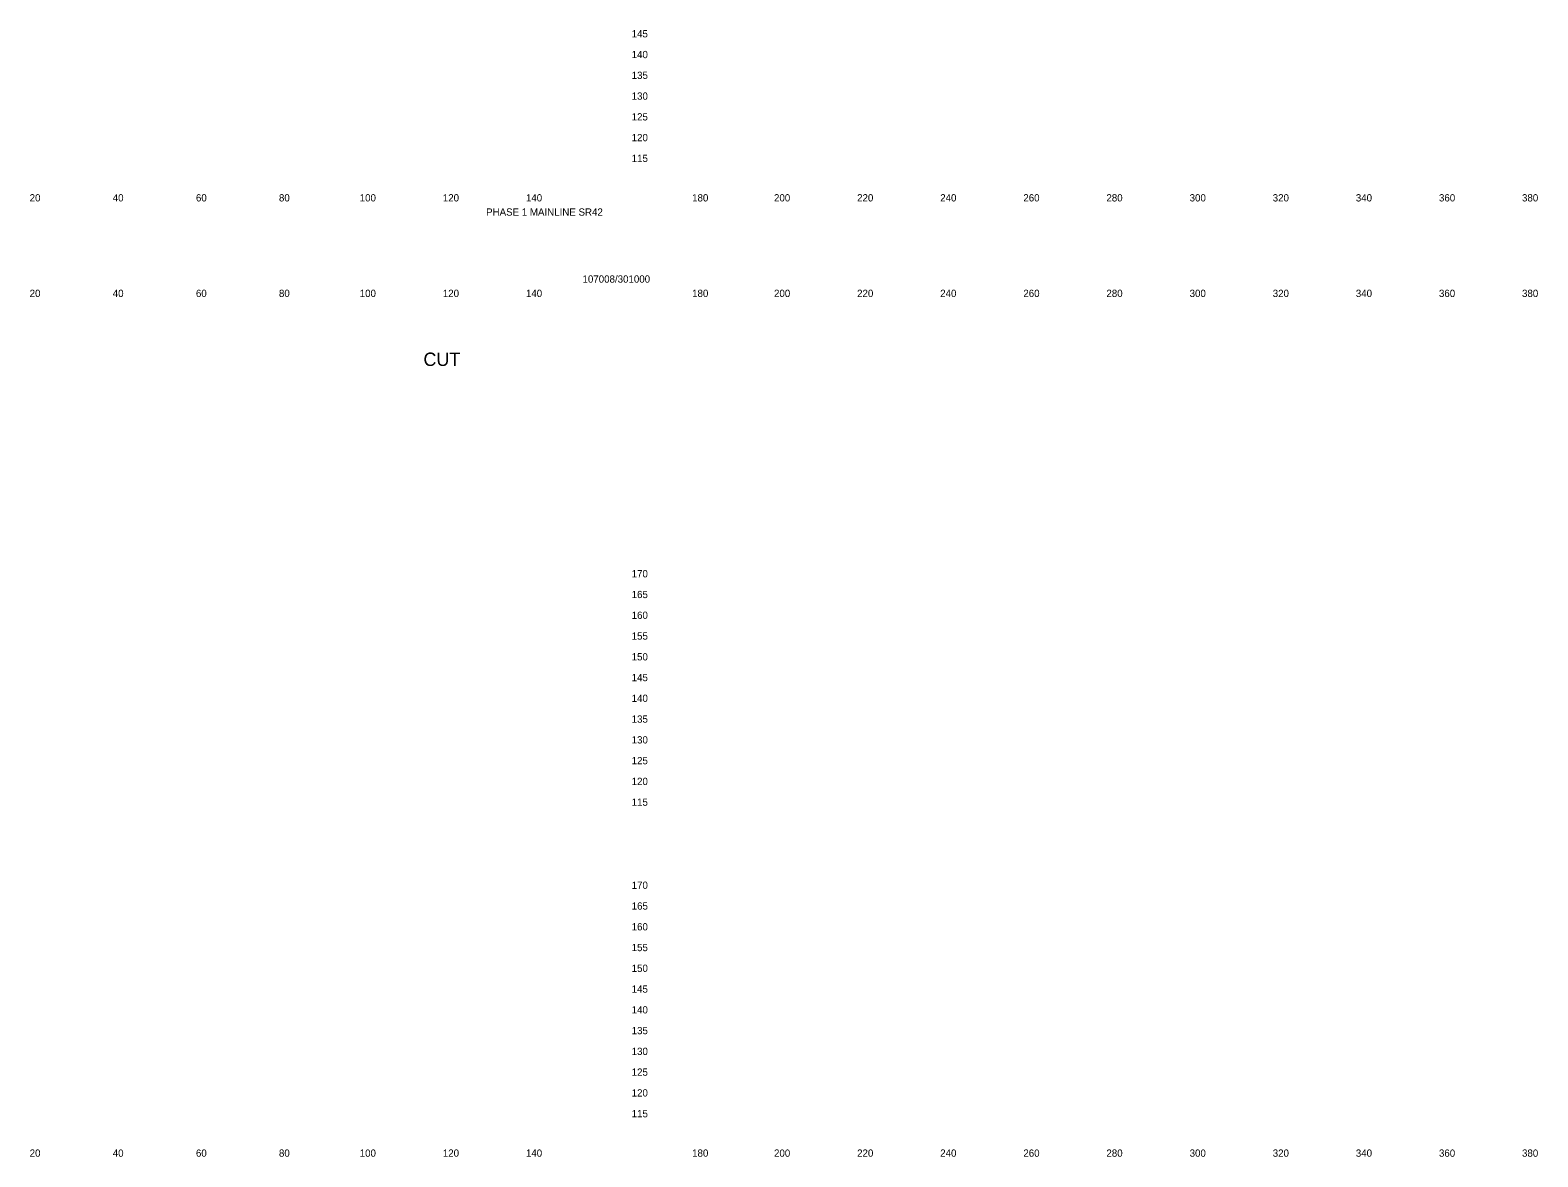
# Model space of a CAD drawing. Extents: x 21281 to 22024, y 6472 to 15198.
# Drawn here: x 21661.4 to 22024.2, y 13835.3 to 14106.6 of the extents above; entities that cross this region are included whole.
import ezdxf

# ---------------------------------------------------------------- set-up
doc = ezdxf.new("R2010")
doc.units = 0
doc.layers.add('XS_SHEET_LABELS_ELEVATION', color=7, linetype='Continuous')
doc.layers.add('XS_SHEET_LABELS_OFFSET', color=7, linetype='Continuous')

msp = doc.modelspace()

# ---------------------------------------------------------------- texts
at = {"layer": 'XS_SHEET_LABELS_ELEVATION'}
for s, p in [('  145  ', (21804.84, 14104.84)), ('  140  ', (21804.84, 14099.84)), ('  135  ', (21804.84, 14094.84)), ('  130  ', (21804.84, 14089.84)), ('  125  ', (21804.84, 14084.84)), ('  120  ', (21804.84, 14079.84)), ('  115  ', (21804.84, 14074.84)), ('  170  ', (21804.84, 13974.84)), ('  165  ', (21804.84, 13969.84)), ('  160  ', (21804.84, 13964.84)), ('  155  ', (21804.84, 13959.84)), ('  150  ', (21804.84, 13954.84)), ('  145  ', (21804.84, 13949.84)), ('  140  ', (21804.84, 13944.84)), ('  135  ', (21804.84, 13939.84)), ('  130  ', (21804.84, 13934.84)), ('  125  ', (21804.84, 13929.84)), ('  120  ', (21804.84, 13924.84)), ('  115  ', (21804.84, 13919.84)), ('  170  ', (21804.84, 13899.84)), ('  165  ', (21804.84, 13894.84)), ('  160  ', (21804.84, 13889.84)), ('  155  ', (21804.84, 13884.84)), ('  150  ', (21804.84, 13879.84)), ('  145  ', (21804.84, 13874.84)), ('  140  ', (21804.84, 13869.84)), ('  135  ', (21804.84, 13864.84)), ('  130  ', (21804.84, 13859.84)), ('  125  ', (21804.84, 13854.84)), ('  120  ', (21804.84, 13849.84)), ('  115  ', (21804.84, 13844.84))]:
    msp.add_text(s, height=1.75, dxfattribs=at).set_placement(p)
at = {"layer": 'XS_SHEET_LABELS_OFFSET'}
for s, height, p in [('  20  ', 1.75, (21659.95, 14065.34)), ('  40  ', 1.75, (21679.95, 14065.34)), ('  60  ', 1.75, (21699.97, 14065.34)), ('  80  ', 1.75, (21719.95, 14065.34)), ('  100  ', 1.75, (21739.39, 14065.34)), ('  120  ', 1.75, (21759.39, 14065.34)), ('  140  ', 1.75, (21779.39, 14065.34)), ('  180  ', 1.75, (21819.39, 14065.34)), ('  200  ', 1.75, (21839.1, 14065.34)), ('  220  ', 1.75, (21859.1, 14065.34)), ('  240  ', 1.75, (21879.1, 14065.34)), ('  260  ', 1.75, (21899.11, 14065.34)), ('  280  ', 1.75, (21919.1, 14065.34)), ('  300  ', 1.75, (21939.13, 14065.34)), ('  320  ', 1.75, (21959.13, 14065.34)), ('  340  ', 1.75, (21979.13, 14065.34)), ('  360  ', 1.75, (21999.14, 14065.34)), ('  380  ', 1.75, (22019.13, 14065.34)), ('PHASE 1 MAINLINE SR42', 1.75, (21771.11, 14061.92)), ('107008/301000', 1.75, (21794.31, 14045.79)), ('  20  ', 1.75, (21659.95, 14042.34)), ('  40  ', 1.75, (21679.95, 14042.34)), ('  60  ', 1.75, (21699.97, 14042.34)), ('  80  ', 1.75, (21719.95, 14042.34)), ('  100  ', 1.75, (21739.39, 14042.34)), ('  120  ', 1.75, (21759.39, 14042.34)), ('  140  ', 1.75, (21779.39, 14042.34)), ('  180  ', 1.75, (21819.39, 14042.34)), ('  200  ', 1.75, (21839.1, 14042.34)), ('  220  ', 1.75, (21859.1, 14042.34)), ('  240  ', 1.75, (21879.1, 14042.34)), ('  260  ', 1.75, (21899.11, 14042.34)), ('  280  ', 1.75, (21919.1, 14042.34)), ('  300  ', 1.75, (21939.13, 14042.34)), ('  320  ', 1.75, (21959.13, 14042.34)), ('  340  ', 1.75, (21979.13, 14042.34)), ('  360  ', 1.75, (21999.14, 14042.34)), ('  380  ', 1.75, (22019.13, 14042.34)), ('CUT', 3.222, (21756.03, 14025.73)), ('  20  ', 1.75, (21659.95, 13835.34)), ('  40  ', 1.75, (21679.95, 13835.34)), ('  60  ', 1.75, (21699.97, 13835.34)), ('  80  ', 1.75, (21719.95, 13835.34)), ('  100  ', 1.75, (21739.39, 13835.34)), ('  120  ', 1.75, (21759.39, 13835.34)), ('  140  ', 1.75, (21779.39, 13835.34)), ('  180  ', 1.75, (21819.39, 13835.34)), ('  200  ', 1.75, (21839.1, 13835.34)), ('  220  ', 1.75, (21859.1, 13835.34)), ('  240  ', 1.75, (21879.1, 13835.34)), ('  260  ', 1.75, (21899.11, 13835.34)), ('  280  ', 1.75, (21919.1, 13835.34)), ('  300  ', 1.75, (21939.13, 13835.34)), ('  320  ', 1.75, (21959.13, 13835.34)), ('  340  ', 1.75, (21979.13, 13835.34)), ('  360  ', 1.75, (21999.14, 13835.34)), ('  380  ', 1.75, (22019.13, 13835.34))]:
    msp.add_text(s, height=height, dxfattribs=at).set_placement(p)

doc.saveas('drawing.dxf')
